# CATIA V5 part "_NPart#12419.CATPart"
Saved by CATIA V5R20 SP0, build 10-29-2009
Part number: Junta tórica Ø12x1
Revision: ANY
Definition: UNKNOWN
Nomenclature: Junta tórica Ø12x1
Source: Unknown
Bounding box of the stored display mesh (mm): x -6.824 to 6.824, y -0.5 to 0.5, z -7 to 7
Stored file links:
  C:\Users\Utente\Desktop\IO LAVORO\3D X SITO CF\CUMSA\3D files AE\AE 041620\_NPart#12419.CATPart
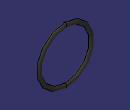
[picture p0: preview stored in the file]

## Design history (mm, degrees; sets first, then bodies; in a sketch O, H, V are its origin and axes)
Body1 "Revolución1" (main body)
  Solid1: solid without history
